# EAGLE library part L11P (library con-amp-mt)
AMP MT CONNECTOR
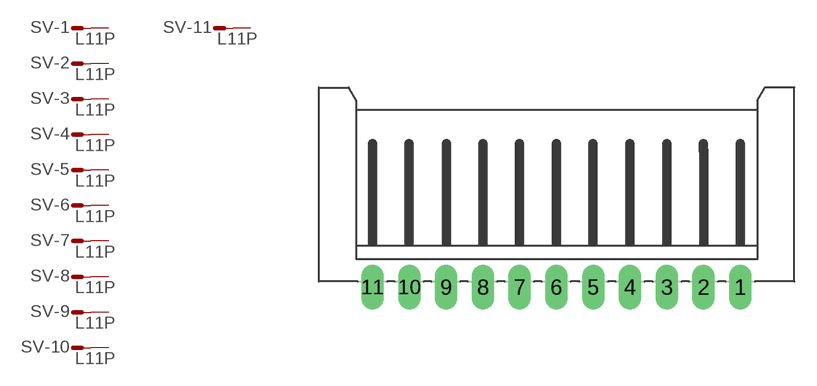
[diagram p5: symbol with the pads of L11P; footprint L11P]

Designator prefix SV; gates -1=M -2=M -3=M -4=M -5=M -6=M -7=M -8=M -9=M -10=M -11=M

## L11P (OC_FARNELL: unknown; OC_NEWARK: unknown)  [L11P]
1  -1:S  pas
2  -2:S  pas
3  -3:S  pas
4  -4:S  pas
5  -5:S  pas
6  -6:S  pas
7  -7:S  pas
8  -8:S  pas
9  -9:S  pas
10  -10:S  pas
11  -11:S  pas

## Footprint L11P (pad centres in mm)
AMP MT CONNECTOR
drill 1.016 long: 1 12.5,-6.25; 2 10,-6.25; 3 7.5,-6.25; 4 5,-6.25; 5 2.5,-6.25; 6 0,-6.25; 7 -2.5,-6.25; 8 -5,-6.25; 9 -7.5,-6.25; 10 -10,-6.25; 11 -12.5,-6.25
